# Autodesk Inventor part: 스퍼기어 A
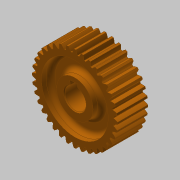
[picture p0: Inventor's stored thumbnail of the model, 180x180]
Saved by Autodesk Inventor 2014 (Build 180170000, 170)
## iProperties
Created: 2020-04
Part Number: 스퍼기어 A
Material: Steel
Document SubType Name: Modeling
Designer: mduedu
Categories: <?xml version="1.0" encoding="UTF-16"?> <MemberInstance><Categories><FamilyTemplate><FamilyTemplateParameter ValueType="xs:double" Id="1" ObjectReferenceKey="da
Density: 7.85 g/cm^3
Mass: 238.005 g
Surface Area: 130.635 cm^2
Volume: 30.3191 cm^3
Appearance: 주황색
CustomPartVersion: 1
Author: mduedu
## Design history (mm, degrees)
sketch "Sketch1"
  geometry: C1 r 28.2 at (0, 0)
  constraints: 1 centre point
  dimensions: "d0" = 56.4 diameter of C1 (= da_da)
extrude "Extrusion1" new body sketch "Sketch1" distance "d1" = 20 (= da_b); taper "d2" = 0 deg
workplane "Work Plane2"
sketch "Sketch2"
  geometry: C1 r 28.2 at (0, 0) reference; C2 r 27 at (0, 0)
  constraints: 1 centre point, 1 coincident
  dimensions: "d3" = 54 diameter of C2 (= da_dw)
feature "피치 지름" sketch "Sketch2" dims "d4" = 10, "d5" = 0
workplane "Work Plane8"
workplane "Work Plane9"
feature "스퍼 기어" dims "da_b" = 20, "da_d" = 54, "da_aw" = 45, "da_da" = 56.4, "da_df" = 51.129, "da_dw" = 54, angle "da_beta" = 0 deg, "da_lefttooth" = 0, "da_righttooth" = 0
node "작업 평면11"
sketch "스케치3"
  geometry: C1 r 12 at (0, 0); C2 r 22 at (0, 0); 1 further point
  constraints: 2 centre point, 2 coincident
  dimensions: "d49" = 24 diameter of C1; "d50" = 44 diameter of C2
extrude "돌출2" cut sketch "스케치3" distance "d51" = 6; taper "d52" = 0 deg
fillet "모깎기1" dims "d53" = 3
sketch "스케치4" dims "d17" = 0
  geometry: L1 (-3.06, 6.296)-(1.921, 6.731); L2 (1.921, 6.731)-(1.68, 9.483); L3 (1.68, 9.483)-(-3.301, 9.047); L4 (-3.301, 9.047)-(-3.06, 6.296); L5 (-3.728, 42.608)-(3.728, -42.608) reference; A1 r 7 centre (0, 0) between (-3.06, 6.296) and (1.921, 6.731); 1 further point
  constraints: 8 end point, 4 perpendicular, 2 point on circle, 1 centre point, 1 coincident
  dimensions: "d54" = 14 diameter of A1; "d63" = 16.3 dimension on A1 L3; "d64" = 5 distance of L2.end L3.end
extrude "돌출3" cut sketch "스케치4" stored distance "d58" = 6; taper "d59" = 0 deg
chamfer "모따기1" distance "d60" = 0.5; stored, may be unused: second distance "d61" = 2, angle "d62" = 45 deg
body "Solid1"
mirror "대칭1"
body "Srf1"
other parameters: "d16" = 45 (= da_aw), "d34" = 5 deg (computed from da_z), "d39" = 0, "d41" = 0, "d43" = 45 (= da_aw), "d46" = 45 (= da_aw), "d47" = 0, "d48" = 0
